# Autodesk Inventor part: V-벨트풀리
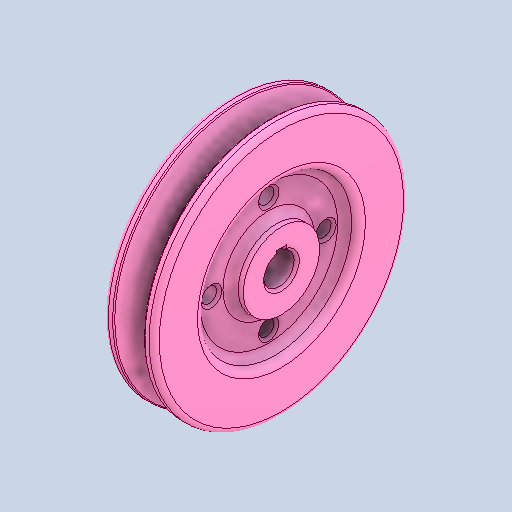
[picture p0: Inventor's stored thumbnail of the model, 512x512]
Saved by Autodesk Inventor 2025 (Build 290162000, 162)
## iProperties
Created: 2024-07
Part Number: V-벨트풀리
Material: 강철, 연강
Document SubType Name: Modeling
Designer: Administrator
Density: 7.86 g/cm^3
Appearance: 기본값
Author: jhkim
Sending System: Autodesk Inventor 2025
Preprocessor: ST-DEVELOPER v20
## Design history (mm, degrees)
feature "솔리드1"
node "솔리드2"
